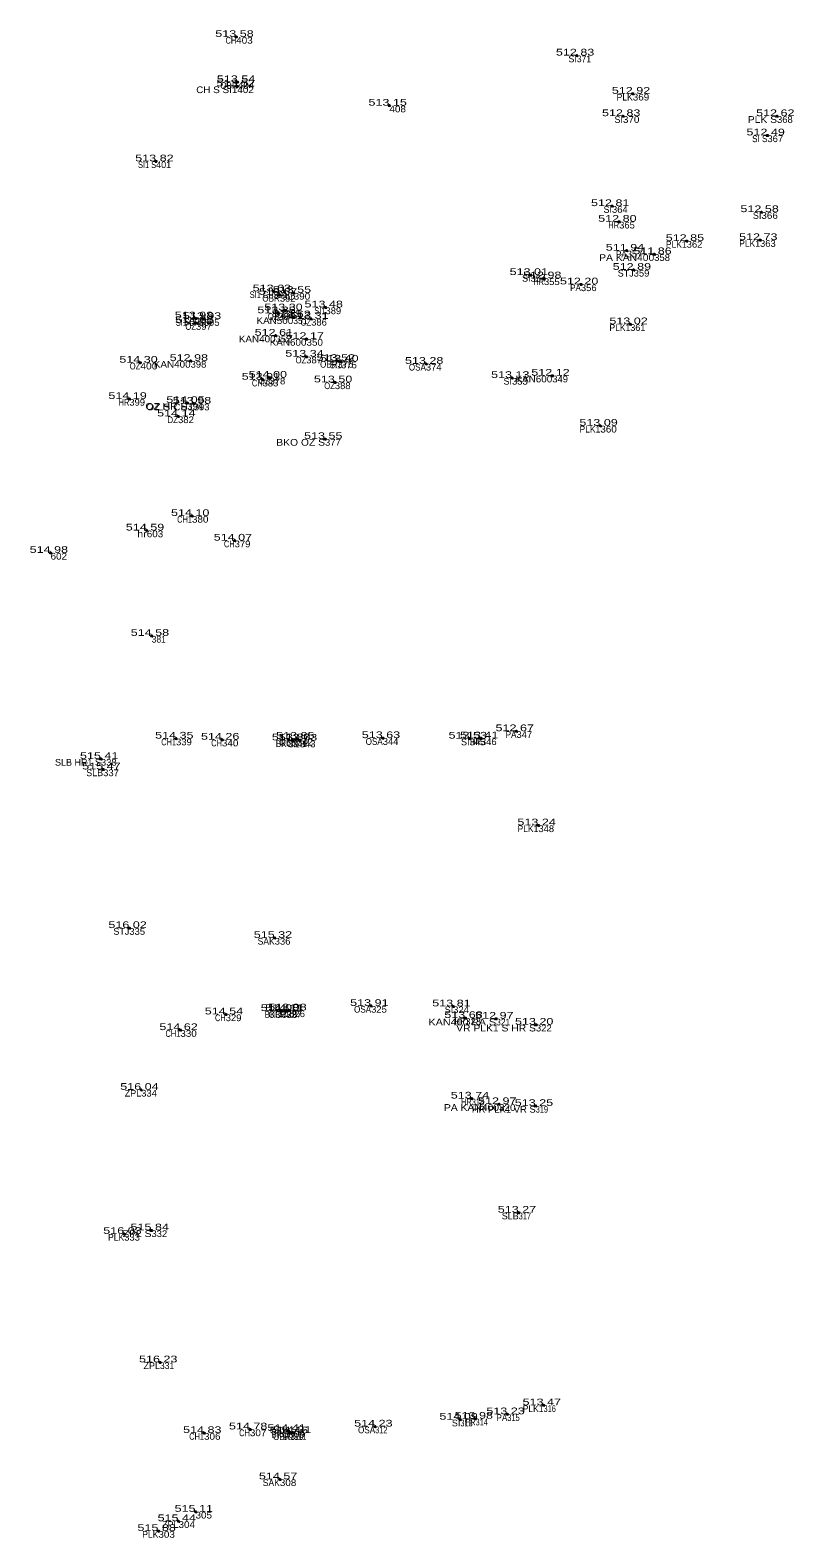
# Model space of a CAD drawing. Extents: x -643086 to -639283, y -1131805 to -1123269.
# Drawn here: x -639408.3 to -639374.2, y -1123547.3 to -1123479.9 of the extents above; entities that cross this region are included whole.
import ezdxf
from ezdxf.enums import TextEntityAlignment as Align

# ---------------------------------------------------------------- set-up
doc = ezdxf.new("R2010")
doc.units = 0
doc.header["$LTSCALE"] = 0.12
doc.header["$PDMODE"] = 32
doc.header["$PDSIZE"] = 0.06
for name, color, linetype in [('1', 7, 'Continuous'), ('2', 7, 'Continuous'), ('3', 7, 'Continuous'), ('4', 7, 'Continuous')]:
    doc.layers.add(name, color=color, linetype=linetype)

msp = doc.modelspace()

# ---------------------------------------------------------------- linework, layer by layer
at = {"layer": '1'}
for p in [(-639399.09, -1123480.2), (-639383.86, -1123481.03), (-639399.04, -1123482.41), (-639399.02, -1123482.22), (-639392.24, -1123483.27), (-639381.36, -1123482.74), (-639381.8, -1123483.74), (-639374.91, -1123483.74), (-639375.34, -1123484.6), (-639402.67, -1123485.76), (-639382.29, -1123487.76), (-639375.61, -1123488.03), (-639381.97, -1123488.46), (-639378.95, -1123489.32), (-639375.67, -1123489.28), (-639381.63, -1123489.75), (-639380.4, -1123489.91), (-639381.32, -1123490.61), (-639385.93, -1123490.84), (-639385.33, -1123490.99), (-639383.68, -1123491.26), (-639397.42, -1123491.57), (-639397.14, -1123491.73), (-639396.52, -1123491.64), (-639400.9, -1123492.78), (-639397.21, -1123492.55), (-639396.9, -1123492.42), (-639396.54, -1123492.73), (-639395.1, -1123492.29), (-639400.89, -1123492.99), (-639400.54, -1123492.81), (-639395.74, -1123492.8), (-639381.47, -1123493.04), (-639397.33, -1123493.55), (-639395.95, -1123493.7), (-639403.38, -1123494.76), (-639401.13, -1123494.68), (-639395.96, -1123494.49), (-639394.56, -1123494.68), (-639394.4, -1123494.71), (-639390.61, -1123494.81), (-639397.6, -1123495.43), (-639386.76, -1123495.44), (-639384.96, -1123495.34), (-639397.91, -1123495.52), (-639394.68, -1123495.64), (-639403.87, -1123496.38), (-639401.28, -1123496.56), (-639400.99, -1123496.59), (-639401.69, -1123497.16), (-639395.12, -1123498.17), (-639382.81, -1123497.58), (-639401.07, -1123501.61), (-639403.09, -1123502.26), (-639399.16, -1123502.71), (-639407.39, -1123503.26), (-639402.87, -1123506.97), (-639401.78, -1123511.56), (-639399.73, -1123511.61), (-639396.56, -1123511.64), (-639396.37, -1123511.57), (-639396.25, -1123511.65), (-639392.54, -1123511.54), (-639388.66, -1123511.56), (-639388.15, -1123511.55), (-639386.56, -1123511.23), (-639405.14, -1123512.47), (-639405.04, -1123512.94), (-639385.58, -1123515.44), (-639403.87, -1123520.03), (-639397.37, -1123520.47), (-639397.06, -1123523.74), (-639396.86, -1123523.74), (-639396.72, -1123523.71), (-639393.06, -1123523.51), (-639389.39, -1123523.53), (-639399.56, -1123523.89), (-639388.85, -1123524.05), (-639387.47, -1123524.08), (-639385.69, -1123524.35), (-639401.59, -1123524.59), (-639403.34, -1123527.26), (-639388.56, -1123527.65), (-639387.34, -1123527.9), (-639385.7, -1123527.98), (-639386.46, -1123532.75), (-639404.1, -1123533.7), (-639402.88, -1123533.54), (-639402.5, -1123539.44), (-639388.39, -1123541.96), (-639386.97, -1123541.76), (-639385.35, -1123541.36), (-639400.53, -1123542.6), (-639398.48, -1123542.44), (-639396.76, -1123542.51), (-639396.66, -1123542.61), (-639396.51, -1123542.6), (-639392.88, -1123542.31), (-639389.07, -1123542), (-639397.14, -1123544.67), (-639401.67, -1123546.54), (-639400.91, -1123546.12), (-639402.57, -1123546.98)]:
    msp.add_point(p, dxfattribs=at)

# ---------------------------------------------------------------- texts
at = {"layer": '2'}
for s, width, p in [('403', 1.1, (-639399.09, -1123480.5)), ('371', 0.95, (-639383.86, -1123481.33)), ('402', 1.1, (-639399.04, -1123482.71)), ('404', 1.1, (-639399.02, -1123482.52)), ('408', 1.1, (-639392.24, -1123483.57)), ('369', 1.1, (-639381.36, -1123483.04)), ('370', 1.1, (-639381.8, -1123484.04)), ('368', 1.05, (-639374.91, -1123484.04)), ('367', 1.05, (-639375.34, -1123484.9)), ('364', 1.05, (-639382.29, -1123488.06)), ('366', 1.1, (-639375.61, -1123488.33)), ('365', 1.05, (-639381.97, -1123488.76)), ('362', 1.05, (-639378.95, -1123489.62)), ('363', 1.05, (-639375.67, -1123489.58)), ('357', 1.05, (-639381.63, -1123490.05)), ('358', 1.05, (-639380.4, -1123490.21)), ('359', 1.05, (-639381.32, -1123490.91)), ('354', 1.05, (-639385.93, -1123491.14)), ('355', 1.05, (-639385.33, -1123491.29)), ('356', 1.05, (-639383.68, -1123491.56)), ('391', 0.95, (-639397.42, -1123491.87)), ('392', 1.05, (-639397.14, -1123492.03)), ('390', 1.1, (-639396.52, -1123491.94)), ('384', 1.05, (-639397.21, -1123492.85)), ('385', 1.05, (-639396.9, -1123492.72)), ('351', 0.95, (-639396.54, -1123493.03)), ('389', 1.05, (-639395.1, -1123492.59)), ('396', 1.1, (-639400.9, -1123493.08)), ('397', 1.05, (-639400.89, -1123493.29)), ('395', 1.05, (-639400.54, -1123493.11)), ('386', 1.05, (-639395.74, -1123493.1)), ('352', 1.05, (-639397.33, -1123493.85)), ('350', 1.1, (-639395.95, -1123494)), ('400', 1.15, (-639403.38, -1123495.06)), ('398', 1.05, (-639401.13, -1123494.98)), ('387', 1.05, (-639395.96, -1123494.79)), ('376', 1.05, (-639394.56, -1123494.98)), ('375', 1.05, (-639394.4, -1123495.01)), ('378', 1.05, (-639397.6, -1123495.73)), ('374', 1.05, (-639390.61, -1123495.11)), ('353', 1.05, (-639386.76, -1123495.74)), ('349', 1.05, (-639384.96, -1123495.64)), ('383', 1.05, (-639397.91, -1123495.82)), ('388', 1.05, (-639394.68, -1123495.94)), ('399', 1.05, (-639403.87, -1123496.68)), ('394', 1.05, (-639401.28, -1123496.86)), ('393', 1.05, (-639400.99, -1123496.89)), ('382', 1.05, (-639401.69, -1123497.46)), ('360', 1.1, (-639382.81, -1123497.88)), ('377', 1.05, (-639395.12, -1123498.47)), ('380', 1.1, (-639401.07, -1123501.91)), ('603', 1.1, (-639403.09, -1123502.56)), ('379', 1.05, (-639399.16, -1123503.01)), ('602', 1.1, (-639407.39, -1123503.56)), ('381', 0.95, (-639402.87, -1123507.27)), ('339', 1.05, (-639401.78, -1123511.86)), ('340', 1.1, (-639399.73, -1123511.91)), ('341', 0.95, (-639396.56, -1123511.94)), ('342', 1.05, (-639396.37, -1123511.87)), ('344', 1.05, (-639392.54, -1123511.84)), ('345', 1.05, (-639388.66, -1123511.86)), ('346', 1.05, (-639388.15, -1123511.85)), ('347', 1.05, (-639386.56, -1123511.53)), ('343', 1.05, (-639396.25, -1123511.95)), ('338', 1.05, (-639405.14, -1123512.77)), ('337', 1.05, (-639405.04, -1123513.24)), ('348', 1.05, (-639385.58, -1123515.74)), ('335', 1.05, (-639403.87, -1123520.33)), ('336', 1.05, (-639397.37, -1123520.77)), ('328', 1.05, (-639397.06, -1123524.04)), ('327', 1.05, (-639396.86, -1123524.04)), ('326', 1.05, (-639396.72, -1123524.01)), ('325', 1.05, (-639393.06, -1123523.81)), ('324', 1.05, (-639389.39, -1123523.83)), ('329', 1.05, (-639399.56, -1123524.19)), ('323', 1.05, (-639388.85, -1123524.35)), ('321', 0.95, (-639387.47, -1123524.38)), ('322', 1.05, (-639385.69, -1123524.65)), ('330', 1.1, (-639401.59, -1123524.89)), ('334', 1.05, (-639403.34, -1123527.56)), ('318', 0.8, (-639388.56, -1123527.95)), ('320', 1.1, (-639387.34, -1123528.2)), ('319', 0.8, (-639385.7, -1123528.28)), ('317', 0.8, (-639386.46, -1123533.05)), ('333', 1.05, (-639404.1, -1123534)), ('332', 1.05, (-639402.88, -1123533.84)), ('331', 0.95, (-639402.5, -1123539.74)), ('314', 0.8, (-639388.39, -1123542.26)), ('315', 0.8, (-639386.97, -1123542.06)), ('316', 0.8, (-639385.35, -1123541.66)), ('306', 1.1, (-639400.53, -1123542.9)), ('307', 1.1, (-639398.48, -1123542.74)), ('309', 1.1, (-639396.76, -1123542.81)), ('310', 0.85, (-639396.66, -1123542.91)), ('311', 0.7, (-639396.51, -1123542.9)), ('312', 0.8, (-639392.88, -1123542.61)), ('313', 0.8, (-639389.07, -1123542.3)), ('308', 1.1, (-639397.14, -1123544.97)), ('304', 1.1, (-639401.67, -1123546.84)), ('305', 1.1, (-639400.91, -1123546.42)), ('303', 1.1, (-639402.57, -1123547.28))]:
    msp.add_text(s, height=0.3, dxfattribs=dict(at, width=width)).set_placement(p)
for s, p in [('401', (-639402.67, -1123486.06)), ('361', (-639381.47, -1123493.34))]:
    msp.add_text(s, height=0.3, dxfattribs=at).set_placement(p)
at = {"layer": '3', "width": 1.4}
for s, p in [('513 58 ', (-639399.09, -1123480.2)), ('512 83 ', (-639383.86, -1123481.03)), ('513 54 ', (-639399.02, -1123482.22)), ('513 52 ', (-639399.04, -1123482.41)), ('512 92 ', (-639381.36, -1123482.74)), ('513 15 ', (-639392.24, -1123483.27)), ('512 83 ', (-639381.8, -1123483.74)), ('512 62 ', (-639374.91, -1123483.74)), ('512 49 ', (-639375.34, -1123484.6)), ('513 82 ', (-639402.67, -1123485.76)), ('512 81 ', (-639382.29, -1123487.76)), ('512 58 ', (-639375.61, -1123488.03)), ('512 80 ', (-639381.97, -1123488.46)), ('512 85 ', (-639378.95, -1123489.32)), ('512 73 ', (-639375.67, -1123489.28)), ('511 94 ', (-639381.63, -1123489.75)), ('511 86 ', (-639380.4, -1123489.91)), ('513 01 ', (-639385.93, -1123490.84)), ('512 98 ', (-639385.33, -1123490.99)), ('512 89 ', (-639381.32, -1123490.61)), ('513 63 ', (-639397.42, -1123491.57)), ('513 55 ', (-639396.52, -1123491.64)), ('512 20 ', (-639383.68, -1123491.26)), ('513 67 ', (-639397.14, -1123491.73)), ('513 48 ', (-639395.1, -1123492.29)), ('513 98 ', (-639400.9, -1123492.78)), ('514 06 ', (-639400.89, -1123492.99)), ('513 93 ', (-639400.54, -1123492.81)), ('513 35 ', (-639397.21, -1123492.55)), ('513 30 ', (-639396.9, -1123492.42)), ('512 62 ', (-639396.54, -1123492.73)), ('513 31 ', (-639395.74, -1123492.8)), ('513 02 ', (-639381.47, -1123493.04)), ('512 61 ', (-639397.33, -1123493.55)), ('512 17 ', (-639395.95, -1123493.7)), ('514 30 ', (-639403.38, -1123494.76)), ('512 98 ', (-639401.13, -1123494.68)), ('513 34 ', (-639395.96, -1123494.49)), ('513 52 ', (-639394.56, -1123494.68)), ('513 40 ', (-639394.4, -1123494.71)), ('513 28 ', (-639390.61, -1123494.81)), ('513 91 ', (-639397.91, -1123495.52)), ('514 00 ', (-639397.6, -1123495.43)), ('513 50 ', (-639394.68, -1123495.64)), ('513 13 ', (-639386.76, -1123495.44)), ('512 12 ', (-639384.96, -1123495.34)), ('514 19 ', (-639403.87, -1123496.38)), ('514 05 ', (-639401.28, -1123496.56)), ('513 98 ', (-639400.99, -1123496.59)), ('514 14 ', (-639401.69, -1123497.16)), ('513 09 ', (-639382.81, -1123497.58)), ('513 55 ', (-639395.12, -1123498.17)), ('514 10 ', (-639401.07, -1123501.61)), ('514 59 ', (-639403.09, -1123502.26)), ('514 07 ', (-639399.16, -1123502.71)), ('514 98 ', (-639407.39, -1123503.26)), ('514 58 ', (-639402.87, -1123506.97)), ('512 67 ', (-639386.56, -1123511.23)), ('514 35 ', (-639401.78, -1123511.56)), ('514 26 ', (-639399.73, -1123511.61)), ('513 80 ', (-639396.56, -1123511.64)), ('513 85 ', (-639396.37, -1123511.57)), ('513 73 ', (-639396.25, -1123511.65)), ('513 63 ', (-639392.54, -1123511.54)), ('513 53 ', (-639388.66, -1123511.56)), ('513 41 ', (-639388.15, -1123511.55)), ('515 41 ', (-639405.14, -1123512.47)), ('515 47 ', (-639405.04, -1123512.94)), ('513 24 ', (-639385.58, -1123515.44)), ('516 02 ', (-639403.87, -1123520.03)), ('515 32 ', (-639397.37, -1123520.47)), ('514 54 ', (-639399.56, -1123523.89)), ('514 08 ', (-639397.06, -1123523.74)), ('514 11 ', (-639396.86, -1123523.74)), ('513 98 ', (-639396.72, -1123523.71)), ('513 91 ', (-639393.06, -1123523.51)), ('513 81 ', (-639389.39, -1123523.53)), ('513 68 ', (-639388.85, -1123524.05)), ('514 62 ', (-639401.59, -1123524.59)), ('512 97 ', (-639387.47, -1123524.08)), ('513 20 ', (-639385.69, -1123524.35)), ('516 04 ', (-639403.34, -1123527.26)), ('513 74 ', (-639388.56, -1123527.65)), ('512 97 ', (-639387.34, -1123527.9)), ('513 25 ', (-639385.7, -1123527.98)), ('513 27 ', (-639386.46, -1123532.75)), ('516 03 ', (-639404.1, -1123533.7)), ('515 84 ', (-639402.88, -1123533.54)), ('516 23 ', (-639402.5, -1123539.44)), ('513 47 ', (-639385.35, -1123541.36)), ('514 09 ', (-639389.07, -1123542)), ('513 98 ', (-639388.39, -1123541.96)), ('513 23 ', (-639386.97, -1123541.76)), ('514 83 ', (-639400.53, -1123542.6)), ('514 78 ', (-639398.48, -1123542.44)), ('514 41 ', (-639396.76, -1123542.51)), ('514 45 ', (-639396.66, -1123542.61)), ('514 31 ', (-639396.51, -1123542.6)), ('514 23 ', (-639392.88, -1123542.31)), ('514 57 ', (-639397.14, -1123544.67)), ('515 11 ', (-639400.91, -1123546.12)), ('515 88 ', (-639402.57, -1123546.98)), ('515 44 ', (-639401.67, -1123546.54))]:
    msp.add_text(s, height=0.3, dxfattribs=at).set_placement(p, align=Align.CENTER)
at = {"layer": '4'}
for s, width, p in [('CH', 0.8, (-639399.09, -1123480.5)), ('CH S SI1', 1.1, (-639399.04, -1123482.71)), ('OBR', 0.9, (-639399.02, -1123482.52)), ('PLK', 0.95, (-639381.36, -1123483.04)), ('PLK S', 1.15, (-639374.91, -1123484.04)), ('SI S', 0.9, (-639375.34, -1123484.9)), ('SI1 S', 0.8, (-639402.67, -1123486.06)), ('HR', 0.8, (-639381.97, -1123488.76)), ('PLK1', 0.95, (-639378.95, -1123489.62)), ('PLK1', 0.95, (-639375.67, -1123489.58)), ('PA KAN400', 1.15, (-639380.4, -1123490.21)), ('PA', 0.9, (-639381.63, -1123490.05)), ('HR', 0.8, (-639385.33, -1123491.29)), ('PA', 0.9, (-639383.68, -1123491.56)), ('SI1 CH', 0.8, (-639397.42, -1123491.87)), ('OBR', 0.9, (-639397.14, -1123492.03)), ('SI1', 0.8, (-639396.52, -1123491.94)), ('KAN500', 1.1, (-639396.54, -1123493.03)), ('OZ', 0.85, (-639397.21, -1123492.85)), ('DZ', 0.9, (-639396.9, -1123492.72)), ('SI1', 0.8, (-639395.1, -1123492.59)), ('SI1 CH1', 0.8, (-639400.54, -1123493.11)), ('SI1', 0.8, (-639400.9, -1123493.08)), ('OZ', 0.85, (-639400.89, -1123493.29)), ('OZ', 0.85, (-639395.74, -1123493.1)), ('PLK1', 0.95, (-639381.47, -1123493.34)), ('KAN400', 1.1, (-639397.33, -1123493.85)), ('KAN600', 1.1, (-639395.95, -1123494)), ('OZ', 0.85, (-639403.38, -1123495.06)), ('KAN400', 1.1, (-639401.13, -1123494.98)), ('OZ', 0.85, (-639395.96, -1123494.79)), ('OBR', 0.9, (-639394.56, -1123494.98)), ('SI1', 0.8, (-639394.4, -1123495.01)), ('OZ', 0.85, (-639397.6, -1123495.73)), ('OSA', 0.9, (-639390.61, -1123495.11)), ('KAN600', 1.1, (-639384.96, -1123495.64)), ('CH', 0.8, (-639397.91, -1123495.82)), ('OZ', 0.85, (-639394.68, -1123495.94)), ('HR', 0.8, (-639403.87, -1123496.68)), ('OZ HR S', 1.15, (-639401.28, -1123496.86)), ('OZ S CH1', 1.15, (-639400.99, -1123496.89)), ('DZ', 0.9, (-639401.69, -1123497.46)), ('PLK1', 0.95, (-639382.81, -1123497.88)), ('BKO OZ S', 1.15, (-639395.12, -1123498.47)), ('CH1', 0.8, (-639401.07, -1123501.91)), ('hr', 1.2, (-639403.09, -1123502.56)), ('CH', 0.8, (-639399.16, -1123503.01)), ('CH1', 0.8, (-639401.78, -1123511.86)), ('CH', 0.8, (-639399.73, -1123511.91)), ('BKO', 0.9, (-639396.56, -1123511.94)), ('OBR', 0.9, (-639396.37, -1123511.87)), ('OSA', 0.9, (-639392.54, -1123511.84)), ('HR', 0.8, (-639388.15, -1123511.85)), ('PA', 0.9, (-639386.56, -1123511.53)), ('SI1', 0.8, (-639396.25, -1123511.95)), ('PLK1', 0.95, (-639385.58, -1123515.74)), ('SAK', 0.95, (-639397.37, -1123520.77)), ('BKO', 0.9, (-639397.06, -1123524.04)), ('OBR', 0.9, (-639396.86, -1123524.04)), ('SI1', 0.8, (-639396.72, -1123524.01)), ('OSA', 0.9, (-639393.06, -1123523.81)), ('CH', 0.8, (-639399.56, -1123524.19)), ('KAN400 PA S', 1.2, (-639387.47, -1123524.38)), ('HR', 0.8, (-639388.85, -1123524.35)), ('VR PLK1 S HR S', 1.15, (-639385.69, -1123524.65)), ('CH1', 0.8, (-639401.59, -1123524.89)), ('HR', 0.8, (-639388.56, -1123527.95)), ('PA KAN400', 1.15, (-639387.34, -1123528.2)), ('HR PLK1 VR S', 1.05, (-639385.7, -1123528.28)), ('PLK', 0.95, (-639404.1, -1123534)), ('ZPL S', 1.15, (-639402.88, -1123533.84)), ('HR', 0.8, (-639388.39, -1123542.26)), ('PA', 0.9, (-639386.97, -1123542.06)), ('PLK1', 0.95, (-639385.35, -1123541.66)), ('CH1', 0.8, (-639400.53, -1123542.9)), ('CH', 0.8, (-639398.48, -1123542.74)), ('BKO', 0.9, (-639396.76, -1123542.81)), ('OBR', 0.9, (-639396.66, -1123542.91)), ('SI1', 0.8, (-639396.51, -1123542.9)), ('OSA', 0.9, (-639392.88, -1123542.61)), ('SAK', 0.95, (-639397.14, -1123544.97)), ('PLK', 0.95, (-639402.57, -1123547.28))]:
    msp.add_text(s, height=0.3, dxfattribs=dict(at, width=width)).set_placement(p, align=Align.RIGHT)
for s, p in [('SI', (-639383.86, -1123481.33)), ('SI', (-639381.8, -1123484.04)), ('SI', (-639382.29, -1123488.06)), ('SI', (-639375.61, -1123488.33)), ('STJ', (-639381.32, -1123490.91)), ('SI', (-639385.93, -1123491.14)), ('SI', (-639386.76, -1123495.74)), ('SI', (-639388.66, -1123511.86)), ('SLB HR1 S', (-639405.14, -1123512.77)), ('SLB', (-639405.04, -1123513.24)), ('STJ', (-639403.87, -1123520.33)), ('SI', (-639389.39, -1123523.83)), ('ZPL', (-639403.34, -1123527.56)), ('SLB', (-639386.46, -1123533.05)), ('ZPL', (-639402.5, -1123539.74)), ('SI', (-639389.07, -1123542.3)), ('ZPL', (-639401.67, -1123546.84))]:
    msp.add_text(s, height=0.3, dxfattribs=at).set_placement(p, align=Align.RIGHT)

doc.saveas('drawing.dxf')
